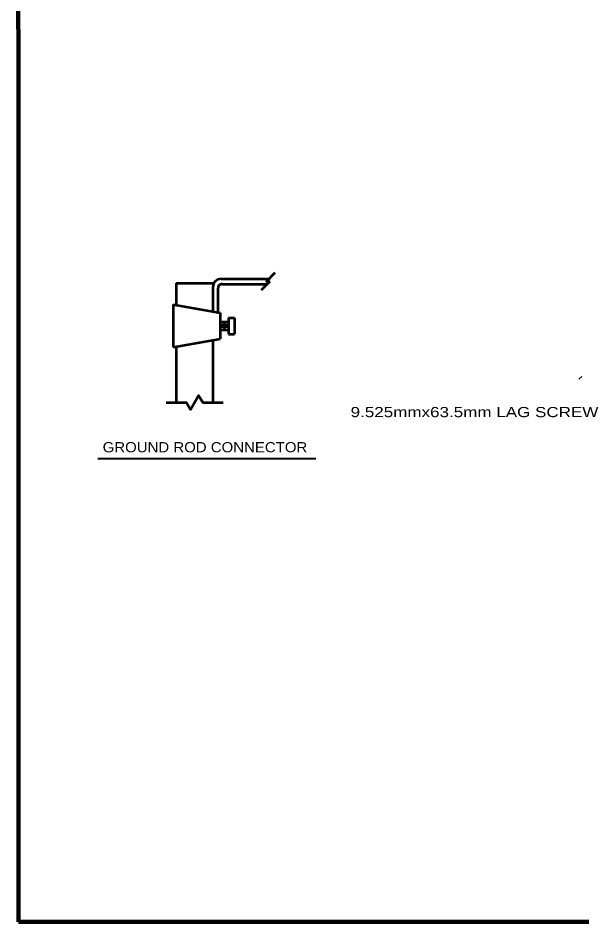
# Model space of a CAD drawing. Extents: x 14808 to 15663, y 10944 to 11488.
# Drawn here: x 14865.2 to 15031.3, y 10955.6 to 11221.9 of the extents above; entities that cross this region are included whole.
import ezdxf

# ---------------------------------------------------------------- set-up
doc = ezdxf.new("R2010")
doc.units = 0
doc.header["$LTSCALE"] = 1.2
doc.layers.add('1', color=7, linetype='Continuous', lineweight=53)

msp = doc.modelspace()

# ---------------------------------------------------------------- linework, layer by layer
at = {"layer": '1'}
for p, q in [((14911.772, 11143.824), (14911.772, 11137.365)), ((14911.772, 11143.824), (14922.888, 11143.824)), ((14922.572, 11142.633), (14922.572, 11135.461)), ((14924.972, 11145.033), (14939.051, 11145.033)), ((14925.272, 11143.533), (14938.615, 11143.533)), ((14939.368, 11144.287), (14936.823, 11141.741)), ((14924.072, 11142.333), (14924.072, 11135.197)), ((14910.872, 11137.524), (14910.872, 11124.935)), ((14910.872, 11137.524), (14924.758, 11135.076)), ((14924.758, 11135.076), (14924.758, 11127.384)), ((14924.758, 11132.424), (14927.158, 11132.424)), ((14925.958, 11130.024), (14925.958, 11132.424)), ((14927.158, 11133.624), (14927.158, 11128.824)), ((14927.158, 11133.624), (14928.958, 11133.624)), ((14928.958, 11133.624), (14928.958, 11128.824)), ((14924.758, 11130.024), (14927.158, 11130.024)), ((14925.358, 11130.624), (14925.358, 11131.824)), ((14926.558, 11130.624), (14926.558, 11131.824)), ((14910.872, 11124.935), (14924.758, 11127.384)), ((14922.572, 11126.998), (14922.572, 11108.724)), ((14927.158, 11128.824), (14928.958, 11128.824)), ((14911.772, 11125.094), (14911.772, 11108.724))]:
    msp.add_line(p, q, dxfattribs=at)
at = {"layer": '1', "lineweight": 35}
msp.add_line((15030.38, 11115.507), (15031.302, 11116.294), dxfattribs=at)
at = {"layer": '1', "lineweight": 40}
msp.add_line((14888.706, 11092.112), (14952.873, 11092.112), dxfattribs=at)
at = {"layer": '1', "lineweight": 158}
msp.add_line((15656.868, 10955.64), (14865.268, 10955.64), dxfattribs=at)
msp.add_lwpolyline([(15656.868, 11481.74), (14865.168, 11481.64), (14865.268, 10955.64)], dxfattribs=at)
at = {"layer": '1'}
for points in [[(14940.877, 11146.859), (14938.332, 11144.314), (14939.368, 11144.287)], [(14908.766, 11108.675), (14914.766, 11108.675), (14915.966, 11106.596), (14918.366, 11110.753), (14919.566, 11108.675), (14925.566, 11108.675)]]:
    msp.add_lwpolyline(points, dxfattribs=at)
for centre, radius, start in [((14924.972, 11142.633), 2.4, 90), ((14925.272, 11142.333), 1.2, 89.99931)]:
    msp.add_arc(centre, radius, start, 180, dxfattribs=at)

# ---------------------------------------------------------------- texts
for s, width, p in [('9.525mmx63.5mm LAG SCREW', 1.25, (14963.168, 11104.329)), ('GROUND ROD CONNECTOR', 1.1, (14890.092, 11093.979))]:
    msp.add_text(s, height=3, dxfattribs=dict(at, width=width)).set_placement(p)

doc.saveas('drawing.dxf')
